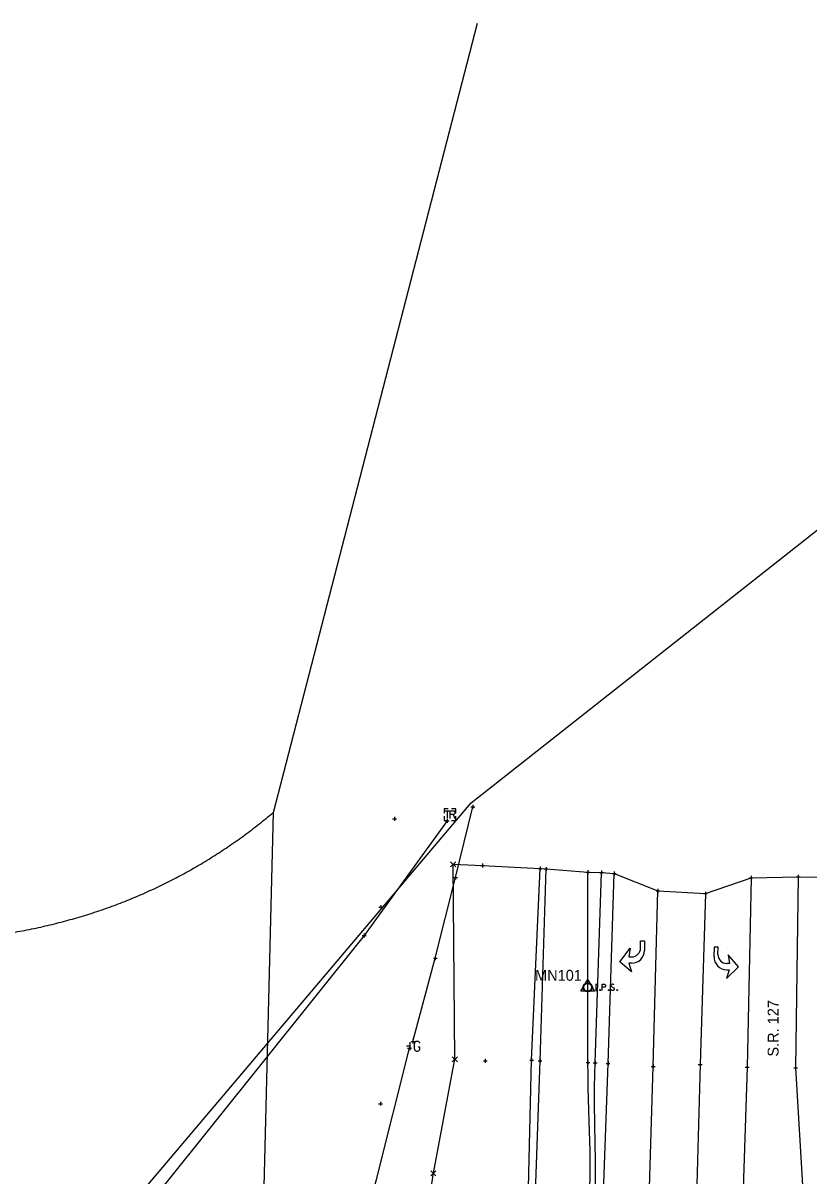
# Model space of a CAD drawing. Extents: x 1391912 to 1392597, y 304167 to 305226.
# Drawn here: x 1392156.2 to 1392358.8, y 304544.7 to 304842 of the extents above; entities that cross this region are included whole.
import ezdxf

# ---------------------------------------------------------------- set-up
doc = ezdxf.new("R2010")
doc.units = 0
for name, color, linetype in [('DV_X_Property_Line', 7, 'Continuous'), ('DV_X_Section_VMS_Line', 7, 'Continuous'), ('PM_X_Channelizing_Line', 7, 'Continuous'), ('PM_X_CL_Double_Solid', 7, 'Continuous'), ('PM_X_Edge_Line', 7, 'Continuous'), ('PV_X_EOP', 7, 'Continuous'), ('PV_X_Shoulder_Aggregate', 7, 'Continuous'), ('RW_X_CL_100_Cardinal_Points', 7, 'Continuous'), ('RW_X_Esmt_SH', 7, 'Continuous'), ('SV_Control_Point', 7, 'Continuous'), ('SV_P_Mon_Cells_Set', 7, 'Continuous'), ('SV_X_Break_Lines', 7, 'Continuous'), ('SV_X_Terrain_Boundary', 7, 'Continuous'), ('SV_X_Text', 7, 'Continuous'), ('SV_X_Toe_of_Slope', 7, 'Continuous'), ('UT_X_FO', 7, 'Continuous'), ('UT_X_Gas', 7, 'Continuous'), ('UT_X_Gas_Cells', 7, 'Continuous'), ('UT_X_Overhead_Combined', 7, 'Continuous'), ('UT_X_Sanitary_Pressure_Line', 7, 'Continuous')]:
    doc.layers.add(name, color=color, linetype=linetype)

msp = doc.modelspace()

# ---------------------------------------------------------------- linework, layer by layer
at = {"layer": 'DV_X_Property_Line'}
for p, q in [((1392310.07, 304599.9), (1392312.73, 304603.42)), ((1392312.73, 304603.42), (1392312.4, 304601.18)), ((1392313.07, 304605.34), (1392313.07, 304605.34)), ((1392315.4, 304603.48), (1392315.4, 304605.34)), ((1392315.4, 304605.34), (1392316.4, 304605.34)), ((1392316.4, 304605.34), (1392316.4, 304602.86)), ((1392334.36, 304603.71), (1392334.32, 304601.23)), ((1392335.36, 304603.69), (1392334.36, 304603.71)), ((1392335.33, 304601.83), (1392335.36, 304603.69)), ((1392337.7, 304603.65), (1392337.7, 304603.65)), ((1392313.07, 304597.34), (1392310.07, 304599.9)), ((1392312.4, 304601.18), (1392313.1, 304601.18)), ((1392340.62, 304598.64), (1392338, 304601.73)), ((1392338, 304601.73), (1392338.3, 304599.48)), ((1392313.07, 304599.58), (1392312.4, 304599.58)), ((1392312.4, 304599.58), (1392313.07, 304597.34)), ((1392313.07, 304597.34), (1392313.07, 304597.34)), ((1392337.57, 304595.65), (1392340.62, 304598.64)), ((1392338.27, 304597.88), (1392337.57, 304595.65)), ((1392338.3, 304599.48), (1392337.59, 304599.49)), ((1392337.6, 304597.89), (1392338.27, 304597.88)), ((1392337.57, 304595.65), (1392337.57, 304595.65))]:
    msp.add_line(p, q, dxfattribs=at)
for centre, radius, start, end in [((1392313.1, 304603.48), 2.3, 270, 360), ((1392313.12, 304602.86), 3.28, 269.0915, 360), ((1392337.6, 304601.17), 3.28, 179.0772, 269.9857), ((1392337.63, 304601.79), 2.3, 179.0772, 269.0772)]:
    msp.add_arc(centre, radius, start, end, dxfattribs=at)
at = {"layer": 'DV_X_Section_VMS_Line'}
for p, q in [((1392266.44, 304624.41), (1392267.77, 304625.74)), ((1392266.44, 304625.74), (1392267.77, 304624.41)), ((1392266.85, 304574.11), (1392268.18, 304575.45)), ((1392266.85, 304575.45), (1392268.18, 304574.11)), ((1392261.31, 304544.71), (1392262.64, 304546.04)), ((1392261.31, 304546.04), (1392262.64, 304544.71))]:
    msp.add_line(p, q, dxfattribs=at)
at = {"layer": 'PM_X_Channelizing_Line'}
for points in [[(1392317.22, 304524.68), (1392318.62, 304572.95), (1392319.87, 304618.22)], [(1392332.09, 304617.5), (1392330.78, 304573.41), (1392329.38, 304523.97)]]:
    msp.add_lwpolyline(points, dxfattribs=at)
at = {"layer": 'PM_X_CL_Double_Solid'}
msp.add_lwpolyline([(1392343.87, 304621.58), (1392342.86, 304572.73), (1392341.27, 304523.17)], dxfattribs=at)
at = {"layer": 'PM_X_Edge_Line'}
for p, q in [((1392307, 304573.68), (1392308.62, 304622.71)), ((1392356.03, 304621.82), (1392355.36, 304572.56)), ((1392305.23, 304524.78), (1392307, 304573.68)), ((1392355.36, 304572.56), (1392357.28, 304539.41))]:
    msp.add_line(p, q, dxfattribs=at)
at = {"layer": 'PV_X_EOP'}
msp.add_line((1392303.68, 304573.91), (1392305.32, 304622.98), dxfattribs=at)
msp.add_open_spline([(1392234.84, 304470.67), (1392243.18, 304472.16), (1392258, 304481.34), (1392281.79, 304488.52), (1392294.5, 304507.17), (1392305.92, 304534.51), (1392303.1, 304556.6), (1392303.68, 304573.91)], degree=3, dxfattribs=at)
at = {"layer": 'PV_X_Shoulder_Aggregate'}
msp.add_line((1392301.83, 304573.96), (1392301.79, 304623.05), dxfattribs=at)
msp.add_open_spline([(1392233.78, 304478.51), (1392243.5, 304480.11), (1392263.28, 304484.58), (1392287.78, 304501.2), (1392305.02, 304533.31), (1392301.84, 304556.01), (1392301.83, 304573.96)], degree=3, dxfattribs=at)
at = {"layer": 'RW_X_CL_100_Cardinal_Points'}
msp.add_line((1392266.24, 304637.89), (1392266.24, 304637.89), dxfattribs=at)
for points in [[(1392265.84, 304639.39), (1392264.74, 304639.39), (1392264.74, 304638.29)], [(1392264.89, 304638.89), (1392266.13, 304638.89)], [(1392265.52, 304638.89), (1392265.52, 304636.89)], [(1392266.35, 304636.89), (1392266.35, 304638.89), (1392267.11, 304638.89), (1392267.19, 304638.88), (1392267.3, 304638.85), (1392267.35, 304638.82), (1392267.39, 304638.78), (1392267.46, 304638.7), (1392267.5, 304638.63), (1392267.54, 304638.5), (1392267.54, 304638.31), (1392267.52, 304638.25), (1392267.49, 304638.15), (1392267.43, 304638.04), (1392267.36, 304638), (1392267.31, 304637.97), (1392267.28, 304637.95), (1392267.24, 304637.93), (1392267.09, 304637.92), (1392266.35, 304637.92)], [(1392267.74, 304638.29), (1392267.74, 304639.39), (1392266.64, 304639.39)], [(1392264.74, 304637.49), (1392264.74, 304636.39), (1392265.84, 304636.39)], [(1392266.64, 304636.39), (1392267.74, 304636.39), (1392267.74, 304637.49)], [(1392267.09, 304637.92), (1392267.54, 304636.89)]]:
    msp.add_lwpolyline(points, dxfattribs=at)
at = {"layer": 'RW_X_Esmt_SH'}
for p, q in [((1392271.67, 304639.91), (1392272.67, 304639.91)), ((1392272.17, 304640.41), (1392272.17, 304639.41)), ((1392272.17, 304639.91), (1392272.17, 304639.91)), ((1392251.47, 304636.8), (1392252.47, 304636.8)), ((1392251.97, 304637.3), (1392251.97, 304636.3)), ((1392251.97, 304636.8), (1392251.97, 304636.8)), ((1392265.05, 304636.24), (1392266.05, 304636.24)), ((1392265.55, 304636.74), (1392265.55, 304635.74)), ((1392265.55, 304636.24), (1392265.55, 304636.24)), ((1392274.13, 304624.77), (1392275.13, 304624.77)), ((1392274.63, 304625.27), (1392274.63, 304624.27)), ((1392274.63, 304624.77), (1392274.63, 304624.77)), ((1392289.02, 304624.01), (1392290.02, 304624.01)), ((1392289.52, 304624.51), (1392289.52, 304623.51)), ((1392289.52, 304624.01), (1392289.52, 304624.01)), ((1392290.53, 304623.86), (1392291.53, 304623.86)), ((1392291.03, 304624.36), (1392291.03, 304623.36)), ((1392291.03, 304623.86), (1392291.03, 304623.86)), ((1392267.19, 304621.63), (1392268.19, 304621.63)), ((1392267.69, 304622.13), (1392267.69, 304621.13)), ((1392267.69, 304621.63), (1392267.69, 304621.63)), ((1392301.29, 304623.05), (1392302.29, 304623.05)), ((1392301.79, 304623.55), (1392301.79, 304622.55)), ((1392301.79, 304623.05), (1392301.79, 304623.05)), ((1392304.82, 304622.98), (1392305.82, 304622.98)), ((1392305.32, 304623.48), (1392305.32, 304622.48)), ((1392305.32, 304622.98), (1392305.32, 304622.98)), ((1392308.12, 304622.71), (1392309.12, 304622.71)), ((1392308.62, 304623.21), (1392308.62, 304622.21)), ((1392308.62, 304622.71), (1392308.62, 304622.71)), ((1392343.37, 304621.58), (1392344.37, 304621.58)), ((1392343.87, 304622.08), (1392343.87, 304621.08)), ((1392343.87, 304621.58), (1392343.87, 304621.58)), ((1392355.53, 304621.82), (1392356.53, 304621.82)), ((1392356.03, 304622.32), (1392356.03, 304621.32)), ((1392356.03, 304621.82), (1392356.03, 304621.82)), ((1392319.37, 304618.22), (1392320.37, 304618.22)), ((1392319.87, 304618.72), (1392319.87, 304617.72)), ((1392319.87, 304618.22), (1392319.87, 304618.22)), ((1392332.09, 304618), (1392332.09, 304617)), ((1392331.59, 304617.5), (1392332.59, 304617.5)), ((1392332.09, 304617.5), (1392332.09, 304617.5)), ((1392247.92, 304614), (1392248.92, 304614)), ((1392248.42, 304614.5), (1392248.42, 304613.5)), ((1392248.42, 304614), (1392248.42, 304614)), ((1392243.65, 304606.72), (1392244.65, 304606.72)), ((1392244.15, 304607.22), (1392244.15, 304606.22)), ((1392244.15, 304606.72), (1392244.15, 304606.72)), ((1392261.98, 304600.86), (1392262.98, 304600.86)), ((1392262.48, 304601.36), (1392262.48, 304600.36)), ((1392262.48, 304600.86), (1392262.48, 304600.86)), ((1392256.22, 304579.38), (1392257.22, 304579.38)), ((1392256.72, 304579.88), (1392256.72, 304578.88)), ((1392256.72, 304579.38), (1392256.72, 304579.38)), ((1392255.32, 304577.61), (1392256.32, 304577.61)), ((1392255.82, 304578.11), (1392255.82, 304577.11)), ((1392255.82, 304577.61), (1392255.82, 304577.61)), ((1392274.87, 304574.38), (1392275.87, 304574.38)), ((1392275.37, 304574.88), (1392275.37, 304573.88)), ((1392275.37, 304574.38), (1392275.37, 304574.38)), ((1392286.82, 304574.56), (1392287.82, 304574.56)), ((1392287.32, 304575.06), (1392287.32, 304574.06)), ((1392287.32, 304574.56), (1392287.32, 304574.56)), ((1392288.98, 304574.36), (1392289.98, 304574.36)), ((1392289.48, 304574.86), (1392289.48, 304573.86)), ((1392289.48, 304574.36), (1392289.48, 304574.36)), ((1392301.33, 304573.96), (1392302.33, 304573.96)), ((1392301.83, 304574.46), (1392301.83, 304573.46)), ((1392301.83, 304573.96), (1392301.83, 304573.96)), ((1392303.18, 304573.91), (1392304.18, 304573.91)), ((1392303.68, 304574.41), (1392303.68, 304573.41)), ((1392303.68, 304573.91), (1392303.68, 304573.91)), ((1392306.5, 304573.68), (1392307.5, 304573.68)), ((1392307, 304574.18), (1392307, 304573.18)), ((1392307, 304573.68), (1392307, 304573.68)), ((1392318.62, 304573.45), (1392318.62, 304572.45)), ((1392330.28, 304573.41), (1392331.28, 304573.41)), ((1392330.78, 304573.91), (1392330.78, 304572.91)), ((1392330.78, 304573.41), (1392330.78, 304573.41)), ((1392342.86, 304573.23), (1392342.86, 304572.23)), ((1392318.12, 304572.95), (1392319.12, 304572.95)), ((1392318.62, 304572.95), (1392318.62, 304572.95)), ((1392342.36, 304572.73), (1392343.36, 304572.73)), ((1392342.86, 304572.73), (1392342.86, 304572.73)), ((1392354.86, 304572.56), (1392355.86, 304572.56)), ((1392355.36, 304573.06), (1392355.36, 304572.06)), ((1392355.36, 304572.56), (1392355.36, 304572.56)), ((1392247.84, 304563.33), (1392248.84, 304563.33)), ((1392248.34, 304563.83), (1392248.34, 304562.83)), ((1392248.34, 304563.33), (1392248.34, 304563.33))]:
    msp.add_line(p, q, dxfattribs=at)
at = {"layer": 'SV_Control_Point'}
msp.add_line((1392301.76, 304593.34), (1392301.76, 304593.34), dxfattribs=at)
msp.add_lwpolyline([(1392300.03, 304592.34), (1392301.76, 304595.34), (1392303.5, 304592.34)], close=True, dxfattribs=at)
msp.add_circle((1392301.76, 304593.34), 1, dxfattribs=at)
at = {"layer": 'SV_P_Mon_Cells_Set'}
for points in [[(1392303.78, 304594.14), (1392304.13, 304594.14)], [(1392303.96, 304592.54), (1392303.96, 304594.14)], [(1392305.52, 304592.54), (1392305.52, 304594.14), (1392306.05, 304594.14), (1392306.11, 304594.12), (1392306.18, 304594.1), (1392306.22, 304594.07), (1392306.25, 304594.05), (1392306.3, 304593.99), (1392306.33, 304593.92), (1392306.35, 304593.82), (1392306.35, 304593.67), (1392306.34, 304593.62), (1392306.32, 304593.54), (1392306.27, 304593.46), (1392306.23, 304593.42), (1392306.2, 304593.39), (1392306.14, 304593.37), (1392306.05, 304593.36), (1392305.52, 304593.36)], [(1392308.53, 304594.02), (1392308.51, 304594.05), (1392308.48, 304594.07), (1392308.38, 304594.11), (1392308.26, 304594.14), (1392308.17, 304594.14), (1392308.14, 304594.14), (1392307.99, 304594.1), (1392307.87, 304594.02), (1392307.79, 304593.92), (1392307.77, 304593.82), (1392307.77, 304593.75), (1392307.79, 304593.65), (1392307.88, 304593.56), (1392308.49, 304593.18), (1392308.54, 304593.13), (1392308.57, 304593.08), (1392308.59, 304593), (1392308.59, 304592.93), (1392308.58, 304592.85), (1392308.57, 304592.8), (1392308.54, 304592.74), (1392308.52, 304592.69), (1392308.5, 304592.65), (1392308.47, 304592.61), (1392308.43, 304592.59), (1392308.39, 304592.56), (1392308.36, 304592.55), (1392308.26, 304592.54), (1392308.1, 304592.54), (1392308, 304592.56), (1392307.86, 304592.65), (1392307.77, 304592.73)], [(1392303.78, 304592.54), (1392304.13, 304592.54)], [(1392304.92, 304592.75), (1392304.97, 304592.75), (1392305.01, 304592.73), (1392305.04, 304592.68), (1392305.04, 304592.61), (1392305.01, 304592.56), (1392304.97, 304592.54), (1392304.92, 304592.54), (1392304.88, 304592.56), (1392304.85, 304592.61), (1392304.85, 304592.68), (1392304.88, 304592.73), (1392304.92, 304592.75)], [(1392307.17, 304592.75), (1392307.22, 304592.75), (1392307.25, 304592.73), (1392307.29, 304592.68), (1392307.29, 304592.61), (1392307.25, 304592.56), (1392307.22, 304592.54), (1392307.17, 304592.54), (1392307.13, 304592.56), (1392307.1, 304592.61), (1392307.1, 304592.68), (1392307.13, 304592.73), (1392307.17, 304592.75)], [(1392309.35, 304592.75), (1392309.4, 304592.75), (1392309.44, 304592.73), (1392309.47, 304592.68), (1392309.47, 304592.61), (1392309.44, 304592.56), (1392309.4, 304592.54), (1392309.35, 304592.54), (1392309.32, 304592.56), (1392309.28, 304592.61), (1392309.28, 304592.68), (1392309.32, 304592.73), (1392309.35, 304592.75)]]:
    msp.add_lwpolyline(points, dxfattribs=at)
msp.add_circle((1392301.76, 304593.34), 1.2, dxfattribs=at)
at = {"layer": 'SV_X_Break_Lines'}
for p, q in [((1392287.32, 304574.56), (1392289.52, 304624.01)), ((1392286.21, 304529.59), (1392287.32, 304574.56))]:
    msp.add_line(p, q, dxfattribs=at)
at = {"layer": 'SV_X_Terrain_Boundary'}
msp.add_lwpolyline([(1392259.36, 304528.55), (1392261.98, 304545.38), (1392267.52, 304574.78), (1392267.11, 304625.07), (1392274.63, 304624.77), (1392289.52, 304624.01), (1392291.03, 304623.86), (1392301.79, 304623.05), (1392305.32, 304622.98), (1392308.62, 304622.71), (1392319.87, 304618.22), (1392332.09, 304617.5), (1392343.87, 304621.58), (1392356.03, 304621.82), (1392361.75, 304621.73)], dxfattribs=at)
at = {"layer": 'SV_X_Toe_of_Slope'}
for p, q in [((1392289.48, 304574.36), (1392291.03, 304623.86)), ((1392287.94, 304528.66), (1392289.48, 304574.36))]:
    msp.add_line(p, q, dxfattribs=at)
at = {"layer": 'UT_X_FO'}
msp.add_lwpolyline([(1392265.55, 304636.24), (1392244.15, 304606.72), (1392191.89, 304541.46), (1392173.6, 304528.19), (1392165.73, 304510.28), (1392162.82, 304507.03)], dxfattribs=at)
at = {"layer": 'UT_X_Gas'}
for points in [[(1392256.72, 304579.38), (1392262.48, 304600.86), (1392267.69, 304621.63), (1392272.17, 304639.91)], [(1392208.68, 304383.14), (1392209.86, 304403.85), (1392217.44, 304431.72), (1392228.1, 304472.01), (1392237.57, 304508.48), (1392247.36, 304543.76), (1392255.82, 304577.61)]]:
    msp.add_lwpolyline(points, dxfattribs=at)
at = {"layer": 'UT_X_Gas_Cells'}
for p, q in [((1392256.01, 304577.16), (1392256.01, 304579.16)), ((1392256.01, 304578.16), (1392255.06, 304578.16))]:
    msp.add_line(p, q, dxfattribs=at)
msp.add_lwpolyline([(1392258.49, 304578.92), (1392258.47, 304579.02), (1392258.41, 304579.12), (1392258.31, 304579.22), (1392258.17, 304579.33), (1392258.07, 304579.37), (1392258, 304579.39), (1392257.88, 304579.41), (1392257.64, 304579.41), (1392257.54, 304579.39), (1392257.48, 304579.37), (1392257.4, 304579.33), (1392257.25, 304579.22), (1392257.15, 304579.08), (1392257.09, 304578.92), (1392257.05, 304578.7), (1392257.01, 304578.39), (1392257.01, 304577.98), (1392257.03, 304577.64), (1392257.11, 304577.38), (1392257.23, 304577.15), (1392257.33, 304577.07), (1392257.44, 304576.99), (1392257.66, 304576.91), (1392257.88, 304576.91), (1392258.09, 304576.95), (1392258.17, 304576.99), (1392258.25, 304577.03), (1392258.33, 304577.11), (1392258.41, 304577.23), (1392258.49, 304577.4), (1392258.49, 304577.9), (1392258.07, 304577.9)], dxfattribs=at)
at = {"layer": 'UT_X_Overhead_Combined'}
for p, q in [((1392271.74, 304640.95), (1392382.27, 304728.11)), ((1392167.24, 304517.47), (1392271.74, 304640.95))]:
    msp.add_line(p, q, dxfattribs=at)
at = {"layer": 'UT_X_Sanitary_Pressure_Line'}
msp.add_line((1392220.79, 304638.44), (1392273.36, 304841.99), dxfattribs=at)
msp.add_lwpolyline([(1392218.1, 304531.61), (1392220.79, 304638.44)], dxfattribs=at)
msp.add_open_spline([(1392152.99, 304607.38), (1392191.41, 304613.83), (1392220.69, 304638.4)], degree=2, dxfattribs=at)

# ---------------------------------------------------------------- texts
at = {"layer": 'SV_X_Text'}
msp.add_text('MN101', height=2.8, dxfattribs=at).set_placement((1392288.19, 304595.04))
msp.add_text('S.R. 127', height=2.8, rotation=90, dxfattribs=at).set_placement((1392350.96, 304575.48))

doc.saveas('drawing.dxf')
